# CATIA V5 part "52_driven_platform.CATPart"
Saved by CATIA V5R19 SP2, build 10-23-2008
Part number: 52_driven_platform
Bounding box of the stored display mesh (mm): x -82.98 to 82.98, y 57.382 to 223.342, z 74.372 to 90.372
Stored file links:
  C:\Documents and Settings\anizard\Bureau\13\52_driven_platform.CATPart
  C:\Documents and Settings\anizard\Bureau\13\anizard.CATProduct
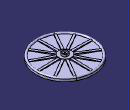
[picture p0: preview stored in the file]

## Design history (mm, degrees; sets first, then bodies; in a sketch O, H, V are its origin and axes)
External parameters (linked from other documents)
  External.diametre = 156 mm
Set1
  Line1: linked copy from another document
  Point1: linked copy from another document
  Plane1: linked copy from another document
  Plane2: linked copy from another document
Body1 (main body)
  Sketch1 on yz-plane, origin (0, 0, 0), H (0, 1, 0), V (0, 0, 1)
    line L1 (147.5619, 86.6719) -> (147.5619, 90.3719)
    line L2 (147.5619, 90.3719) -> (150.3619, 90.3719)
    line L3 (150.3619, 90.3719) -> (150.3619, 84.8719)
    line L4 (150.3619, 84.8719) -> (158.1119, 84.8719)
    line L5 (158.1119, 84.8719) -> (158.1119, 80.6219)
    line L6 (158.1119, 80.6219) -> (217.3619, 80.6219)
    point P8 (223.3619, 80.6219)
    line L7 (223.3619, 80.6219) -> (223.3619, 74.3719)
    line L8 (223.3619, 74.3719) -> (153.8619, 74.3719)
    line L9 (153.8619, 74.3719) -> (153.8619, 78.3719)
    line L10 (153.8619, 78.3719) -> (142.8619, 78.3719)
    line L11 (142.8619, 78.3719) -> (142.8619, 86.6719)
    axis line L12 (140.3619, 136.848) -> (140.3619, 65.1272)
    point P13 (140.3619, 136.848)
    reference projected line E1 (140.3619, -190) -> (140.3619, 190) from Line1
    line L13 (142.8619, 86.6719) -> (147.5619, 86.6719)
    reference intersected line E2 through (0, 74.3719) direction (-1, 0) from Plane1
    reference projected line E3 (140.3619, -210.6281) -> (140.3619, 169.3719) from Line1
    arc A1 centre (220.3619, 80.6219) radius 3 from (223.3619, 80.6219) to (217.3619, 80.6219) ccw
    reference intersected line E4 through (0, 90.3719) direction (-1, 0) from Plane2
    distance L12 L3 = 10
    distance L12 L1 = 7.2
    distance L8 L4 = 10.5
    distance L5 L12 = 17.75
    distance L10 L8 = 4
    distance L12 L9 = 13.5
    distance L13 L4 = 1.8
    distance L6 L13 = 6.05
    distance L7 E3 = 83 {= External.diametre /2+5mm}
    radius A1 = 3
    distance L11 L12 = 2.5
    vertical: L1 V, L3 V, L5 V, L7 V, L9 V, L12 V, L11 V
    horizontal: L2 H, L4 H, L6 H, L8 H, L10 H, L13 H
    coincidence: P13 E1, L8 E2, P8 L6, L2 E4
    tangency: A1 L7
  Shaft1: profile Sketch1, axis Sketch1.L12, angle 360
  Sketch2 on yz-plane, origin (0, 0, 0), H (0, 1, 0), V (0, 0, 1)
    point P1 (157.3619, 83.8719)
    line L1 (145.3619, 80.6219) -> (221.3619, 80.6219)
    line L2 (221.3619, 80.6219) -> (221.3619, 82.1219)
    line L3 (221.3619, 82.1219) -> (157.3619, 83.8719)
    line L4 (145.3619, 80.6219) -> (145.3619, 83.8719)
    line L5 (145.3619, 83.8719) -> (157.3619, 83.8719)
    reference projected line E1 (140.3619, -210.6281) -> (140.3619, 169.3719) from Line1
    reference projected line E2 (140.3619, -210.6281) -> (140.3619, 169.3719) from Line1
    reference intersected line E3 through (0, 80.6219) direction (1, 0) from face of Shaft1 from Sketch1.L6
    reference projected line E4 (140.3619, -210.6281) -> (140.3619, 169.3719) from Line1
    distance E1 L2 = 81 {= External.diametre /2+3mm}
    distance P1 E2 = 17
    length L2 = 1.5
    distance E4 L4 = 5
    distance L1 L5 = 3.25
    horizontal: L1 H, L5 H
    vertical: L2 V, L4 V
    coincidence: L1 E3
  Pad1: profile Sketch2, direction (1, 0, 0), length 3, mirrored extent
  CircPattern1: of Pad1, instances 13, angular step 30, axis from Line1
